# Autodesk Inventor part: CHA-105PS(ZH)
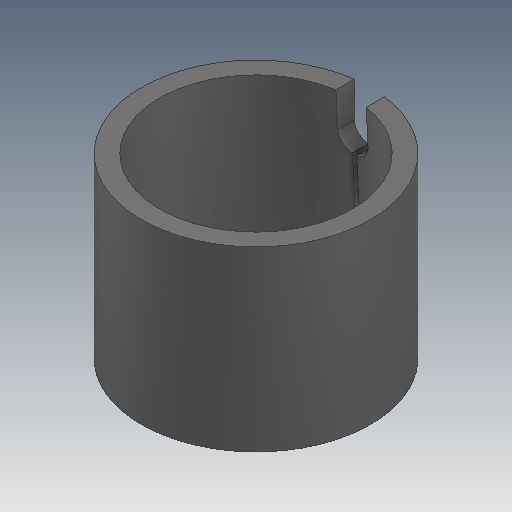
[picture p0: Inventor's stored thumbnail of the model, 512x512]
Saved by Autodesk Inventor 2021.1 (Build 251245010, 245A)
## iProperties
Created: 2021-05
Part Number: CHA-105PS(ZH)
Material: Ogólny
Document SubType Name: Modeling
Designer: user
Density: 1 g/cm^3
Appearance: Domyślna
Author: user
Revision Number: ÈÎºÎ
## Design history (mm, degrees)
feature "ÇÐ³ý-À­Éì1"
node "Bryła1"
